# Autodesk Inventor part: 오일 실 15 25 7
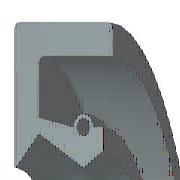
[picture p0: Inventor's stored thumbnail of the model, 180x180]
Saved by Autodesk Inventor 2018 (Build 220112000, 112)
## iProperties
Created: 2012-02
Part Number: 오일 실 15 25 7
Material: 고무
Description: 오일-실
Document SubType Name: Modeling
Standard: KS B 2804
Designer: mduedu
Standards Organization: KS
Language: ko-KR
Size Designation: D - 15 25 7
Categories: <MemberInstance><Categories><Category DisplayName="샤프트 부품" InternalName="7f7aeb1f-a693-4053-b835-cee3144e0d98" Mnemonic="SHFT"><Category DisplayName="실링" Intern
Density: 0.93 g/cm^3
Appearance: 고무 - 검은색 - 버전 1.1
IsCustomPart: 1
Author: mduedu
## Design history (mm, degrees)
revolve "본체" stored, may be unused: angle "d17" = 90 deg
revolve "스프링1" stored, may be unused: angle "d18" = 90 deg
body "Solid1"
sketch "스케치1"
  geometry: L1 (0, 12.5)-(7, 12.5); L2 (7, 10.75)-(1.75, 10.75); L3 (1.75, 9.25)-(4.9, 7.5); L4 (4.9, 7.5)-(0, 7.5); L5 (0, 0)-(9.586, 0) reference; L6 (4.9, 7.5)-(6.3, 8.375); L7 (0, 18)-(0, -3) reference; L8 (-1.941, 0)-(11.507, 0) reference; L9 (4.2, 9.6)-(1.75, 10.09); L10 (1.75, 10.09)-(1.75, 10.75); L11 (0, 12.5)-(0, 7.588); L12 (4.9, 7.5)-(0, 7.5); L13 (1.75, 9.25)-(0.152, 7.528); L14 (7, 12.5)-(7, 10.75); L15 (5.6, 9.6)-(6.3, 9.6); L16 (6.3, 9.6)-(6.3, 8.375); C1 r 0.455 at (4.9, 9.6); A1 r 0.7 centre (4.9, 9.6) between (5.6, 9.6) and (4.2, 9.6); A2 r 0.088 centre (0.088, 7.588) between (0, 7.588) and (0.152, 7.528); 1 further point
  constraints: 28 end point, 5 horizontal alignment, 5 point on line, 4 point on circle, 4 vertical alignment, 3 centre point, 3 tangent, 2 collinear, 2 horizontal, 2 perpendicular, 1 coincident, 1 parallel
  dimensions: "d0" = 25 diameter of L1 L5 (= SD2); "d1" = 1.75 distance of L1.end L2.start (= SD); "d2" = 0.91 diameter of C1 (= SPDI); "d3" = 1.4 diameter of A1 (= SPDA); "d4" = 15 diameter of L3.end L5 (= NND); "d5" = 18.5 diameter of L3.start L5 (= TKDM); "d7" = 20.18 diameter of L9.end L5 (= TKDM + 0.24 x SWDT); "d8" = 1.75 distance between parallel lines of L11 L10 (= SD); "d9" = 4.9 distance from line of L11 C1.centre (= SPDST); "d10" = 19.2 diameter of C1.centre L5 (= HLDM); "d11" = 0.0875 radius of A2 (= 0.25 x LAB); "d12" = 6.3 distance between parallel lines of L11 L16 (= SDI); "d13" = 16.75 diameter of L6.end L5 (= ABDM); "d14" = 7 distance from line of L11 L1.end (= SWDT)
fillet "모깎기1" dims "d6" = 0.3 (= RR)
other parameters: "SD2" = 25 [user parameter; used in 1 equation term], "SWDT" = 7 [user parameter; used in 2 equation terms], "RR" = 0.3 [user parameter; used in 1 equation term], "SD" = 1.75 [user parameter; used in 2 equation terms], "NND" = 15 [user parameter; used in 1 equation term], "SPDA" = 1.4 [user parameter; used in 1 equation term], "SPDI" = 0.91 [user parameter; used in 1 equation term], "TKDM" = 18.5 [user parameter; used in 2 equation terms], "HLDM" = 19.2 [user parameter; used in 1 equation term], "ABDM" = 16.75 [user parameter; used in 1 equation term], "SDI" = 6.3 [user parameter; used in 1 equation term], "SPDST" = 4.9 [user parameter; used in 1 equation term], "LAB" = 0.35 [user parameter; used in 1 equation term], "d15" = 0, "d16" = 0, "d19" = 0
